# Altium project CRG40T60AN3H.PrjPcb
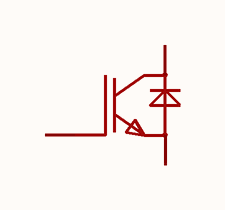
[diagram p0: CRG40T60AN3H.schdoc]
1 sheet, 1 parts. Net scope: global (net labels, ports and power ports of the same name join across sheets).

## Sheet CRG40T60AN3H.schdoc
size 127 x 101 mm

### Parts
Q?  crg40t60an3h  [TO-3P-3_L15.5-W4.8-P5.45-L]  (value not drawn)

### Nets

Not connected (* = marked no-connect by the designer): Q? 1(G) 2(C) 3(E)

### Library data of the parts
Q? = crg40t60an3h: IGBT类型:FS(场截止);耗散功率(Pd):280W;集射极击穿电压(Vces):600V;集电极电流(Ic):40A;; Manufacturer: CRMICRO(华润微); AddInBom: yes; ModelId: 7cf9df9fb3664f61944d1ba67e155084; ModelTransform: 610.235,189.3697,0,0,0,0,0,25,-196.85; Pd - Power Dissipation: 280W; Collector-Emitter Breakdown Voltage (Vces): 600V; Current - Collector(Ic): 40A; Current - Collector Pulsed (Icm): 120A; Vce Saturation(VCE(sat)): 1.9V; Gate-Emitter Threshold Voltage (Vge(th)@Ic): 3.5V@1mA; Gate Charge(Qg): 239nC@15V; Input Capacitance(Cies): 3.453nF; Output Capacitance(Coes): 141pF; Reverse Transfer Capacitance (Cres): 76pF; Td(on): 46.8ns; Td(off): 147.7ns; Turn-On Energy (Eon): 1.11mJ; Switching Energy(Eoff): 710uJ; Reverse Recovery Time(trr): 80ns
